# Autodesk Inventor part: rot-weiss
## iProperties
Created: 2004-10
Part Number: rot-weiss
Document SubType Name: Modeling
Designer: sahrens
Manufacturer: Standard
Standards Organization: Custom
Author: sahrens
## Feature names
1. Extrusion1
2. Rundung2 [Fillet]
